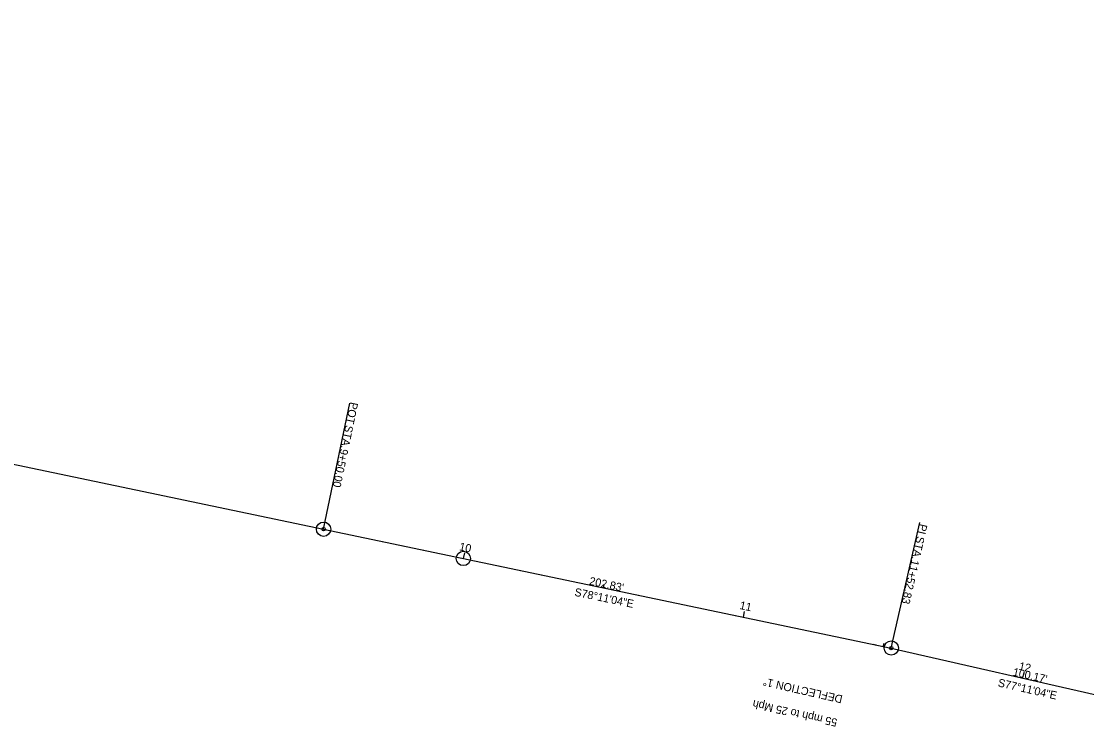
# Model space of a CAD drawing. Extents: x 1815851 to 1817341, y 427933 to 428286.
# Drawn here: x 1816595.8 to 1816968.4, y 428036.6 to 428283.1 of the extents above; entities that cross this region are included whole.
import ezdxf

# ---------------------------------------------------------------- set-up
doc = ezdxf.new("R2010")
doc.units = 0
for name, color, linetype in [('BR_P_Beam_Object', 7, 'Continuous'), ('BR_P_Rail_Object', 7, 'Continuous'), ('BR_P_Sub_Centerline', 7, 'Continuous'), ('Default', 7, 'Continuous'), ('PV_P_EOP', 7, 'Continuous'), ('RW_X_CL', 7, 'Continuous'), ('Z-MEDIAN', 7, 'Continuous'), ('Z-PVMT-BRK', 7, 'Continuous')]:
    doc.layers.add(name, color=color, linetype=linetype)

msp = doc.modelspace()

# ---------------------------------------------------------------- linework, layer by layer
at = {"layer": 'BR_P_Rail_Object'}
for p, q in [((1816701.49, 428105.63), (1816900.03, 428064.1)), ((1816900.03, 428064.1), (1816997.7, 428041.88))]:
    msp.add_line(p, q, dxfattribs=at)
at = {"layer": 'BR_P_Sub_Centerline'}
for centre in [(1816701.49, 428105.63), (1816750.38, 428095.41), (1816900.03, 428064.1)]:
    msp.add_circle(centre, 2.5, dxfattribs=at)
at = {"layer": 'Default'}
for p, q in [((1815853.09, 428283.11), (1816900.03, 428064.1)), ((1816893.7, 428065.42), (1816894.78, 428065.19)), ((1816900.03, 428064.1), (1816997.7, 428041.88))]:
    msp.add_line(p, q, dxfattribs=at)
at = {"layer": 'RW_X_CL'}
for p, q in [((1816701.49, 428105.63), (1816710.7, 428149.68)), ((1816900.03, 428064.1), (1816910.01, 428107.98))]:
    msp.add_line(p, q, dxfattribs=at)
for centre in [(1816701.49, 428105.63), (1816900.03, 428064.1)]:
    msp.add_circle(centre, 0.6, dxfattribs=at)
at = {"layer": 'Z-MEDIAN'}
for p, q in [((1816701.49, 428105.63), (1816701.73, 428106.81)), ((1816750.43, 428095.39), (1816750.84, 428097.35)), ((1816799.37, 428085.16), (1816799.62, 428086.33)), ((1816848.31, 428074.92), (1816848.72, 428076.88)), ((1816897.25, 428064.68), (1816897.5, 428065.85)), ((1816946.02, 428053.64), (1816946.46, 428055.59))]:
    msp.add_line(p, q, dxfattribs=at)

# ---------------------------------------------------------------- texts
at = {"layer": 'BR_P_Beam_Object'}
for s, rotation, p in [('S78°11\'04"E', 348.1844, (1816789.07, 428082.41)), ('S77°11\'04"E', 347.1844, (1816937.13, 428050.74))]:
    msp.add_text(s, height=2.8, rotation=rotation, dxfattribs=at).set_placement(p)
at = {"layer": 'PV_P_EOP'}
for s, p in [('DEFLECTION 1°', (1816883.2, 428047.48)), ('55 mph to 25 Mph', (1816881.34, 428039.29))]:
    msp.add_text(s, height=2.8, rotation=167.1844, dxfattribs=at).set_placement(p)
at = {"layer": 'RW_X_CL'}
for s, rotation, p in [('POT', 258.1844, (1816710.86, 428150.22)), (' STA. ', 258.1844, (1816709.39, 428143.17)), ('9+50.00', 258.1844, (1816707.45, 428133.92)), ('PI', 257.1844, (1816909.98, 428107.68)), (' STA. ', 257.1844, (1816909.23, 428104.37)), ('11+52.83', 257.1844, (1816907.13, 428095.16))]:
    msp.add_text(s, height=2.8, rotation=rotation, dxfattribs=at).set_placement(p)
at = {"layer": 'Z-MEDIAN'}
for s, rotation, p in [('10', 348.1844, (1816748.76, 428098.3)), ('11', 348.1844, (1816846.83, 428077.78)), ('12', 347.1844, (1816944.46, 428056.56))]:
    msp.add_text(s, height=2.8, rotation=rotation, dxfattribs=at).set_placement(p)
at = {"layer": 'Z-PVMT-BRK'}
for s, rotation, p in [("202.83'", 348.1844, (1816794.23, 428086.28)), ("100.17'", 347.1844, (1816942.36, 428054.51))]:
    msp.add_text(s, height=2.8, rotation=rotation, dxfattribs=at).set_placement(p)

doc.saveas('drawing.dxf')
